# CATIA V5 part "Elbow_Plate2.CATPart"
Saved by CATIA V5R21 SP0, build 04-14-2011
Part number: Elbow_Plate2
Bounding box of the stored display mesh (mm): x 0 to 3, y -50.316 to 4.684, z -50.993 to 11
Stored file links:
  F:\教程\Robotic_Arm_Arduino_Kinect\机械臂CAD\Arm_Detailed_Design_Assembly\Elbow_Plate2.CATPart
  C:\Users\Administrator\Desktop\arm\plate1.CATPart
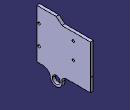
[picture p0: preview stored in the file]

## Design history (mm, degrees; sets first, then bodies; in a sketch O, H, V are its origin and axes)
Body1 (main body)
  Sketch1 on yz-plane, origin (0, 0, 0), H (0, 1, 0), V (0, 0, 1)
    line L1 (4.6838, 6) -> (-24.3574, 6)
    line L2 (-50.3162, -0.2265) -> (-50.3162, -39)
    line L3 (-20.5182, -39) -> (5.4818, -39)
    line L4 (4.6838, -25.3859) -> (4.6838, 6)
    point P3 (-50.3162, -39)
    circle A1 centre (-30.3162, -45) radius 4
    point P4 (-30.3162, -45)
    arc A2 centre (-30.3162, -45) radius 6 from (-24.4374, -43.8) to (-36.2546, -45.8571) cw
    arc A3 centre (-20.5182, -43) radius 4 from (-24.4374, -43.8) to (-20.5182, -39) cw
    line L5 (-50.3162, -39) -> (-44.1726, -39)
    arc A4 centre (-44.1726, -47) radius 8 from (-36.2546, -45.8571) to (-44.1726, -39) ccw
    line L6 (-50.3162, -0.2265) -> (-50.3162, 11)
    line L7 (-50.3162, 11) -> (-30.3162, 11)
    line L8 (-30.3162, 11) -> (-24.3574, 6)
    line L9 (4.6838, -25.3859) -> (4.6838, -39)
    point P16 (4.6838, -39)
    line L10 (4.6838, -39) -> (5.4818, -39)
    axis line L11 (-22.0185, 29.2882) -> (-22.0185, -102.7112)
    circle A5 centre (-47.8162, -4) radius 1.25
    point P19 (-47.8162, -4)
    circle A6 centre (-47.8162, -24) radius 1.25
    point P20 (-47.8162, -24)
    circle A7 centre (-12.8162, -2) radius 1.25
    point P21 (-12.8162, -2)
    circle A8 centre (-12.8162, -19) radius 1.25
    point P22 (-12.8162, -19)
    distance L2 L4 = 55
    radius A1 = 4
    radius A2 = 6
    radius A3 = 4
    radius A4 = 8
    distance P4 H = 45
    distance L1 L3 = 45
    distance L2 P4 = 20
    length L3 = 26
    distance L7 L5 = 50
    angle L8 L7 = 140
    length L7 = 20
    distance P20 L5 = 15
    distance P19 L7 = 15
    radius A6 = 1.25
    radius A5 = 1.25
    distance P19 L2 = 2.5
    distance P20 L2 = 2.5
    radius A7 = 1.25
    distance P21 L1 = 8
    distance P21 L2 = 37.5
    radius A8 = 1.25
    distance P22 L2 = 37.5
    distance L1 P22 = 25
    horizontal: L1 H, L3 H, L7 H
    vertical: L2 V, L4 V, L6 V, L9 V, L11 V
    tangency: A2 L3, A3 A2, A3 L3, L5 A2, A4 A2, A4 L5, L10 A2
    coincidence: L3 P3, P16 L3
    fix: L4
  Pad1: profile Sketch1, direction (1, 0, 0), length 3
